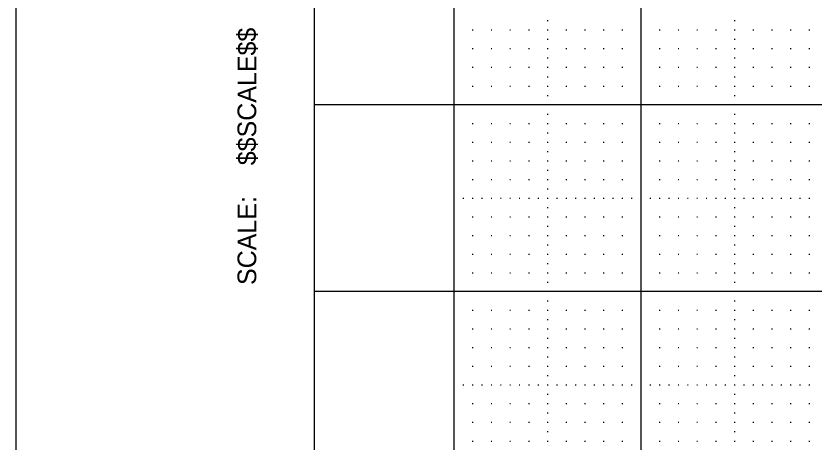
# Model space of a CAD drawing. Extents: x -1.6 to 32.4, y -0.7 to 21.3.
# Drawn here: x -1.598 to 2.67, y 2.487 to 4.768 of the extents above; entities that cross this region are included whole.
import ezdxf

# ---------------------------------------------------------------- set-up
doc = ezdxf.new("R2010")
doc.units = 0
for name, color, linetype in [('Level 1', 7, 'Continuous'), ('Level 5', 7, 'Continuous'), ('Level 63', 7, 'Continuous'), ('R_Border_Dark', 7, 'Continuous')]:
    doc.layers.add(name, color=color, linetype=linetype)

msp = doc.modelspace()

# ---------------------------------------------------------------- linework, layer by layer
at = {"layer": 'Level 1'}
msp.add_line((-0.001, -0.001), (-0.001, 20.545), dxfattribs=at)
at = {"layer": 'Level 5'}
for p, q in [((1.2425, 4.743), (1.2475, 4.743)), ((2.2425, 4.743), (2.2475, 4.743)), ((0.8425, 4.693), (0.8475, 4.693)), ((0.9425, 4.693), (0.9475, 4.693)), ((1.0425, 4.693), (1.0475, 4.693)), ((1.1425, 4.693), (1.1475, 4.693)), ((1.2425, 4.693), (1.2475, 4.693)), ((1.3425, 4.693), (1.3475, 4.693)), ((1.4425, 4.693), (1.4475, 4.693)), ((1.5425, 4.693), (1.5475, 4.693)), ((1.6425, 4.693), (1.6475, 4.693)), ((1.8425, 4.693), (1.8475, 4.693)), ((1.9425, 4.693), (1.9475, 4.693)), ((2.0425, 4.693), (2.0475, 4.693)), ((2.1425, 4.693), (2.1475, 4.693)), ((2.2425, 4.693), (2.2475, 4.693)), ((2.3425, 4.693), (2.3475, 4.693)), ((2.4425, 4.693), (2.4475, 4.693)), ((2.5425, 4.693), (2.5475, 4.693)), ((2.6425, 4.693), (2.6475, 4.693)), ((1.2425, 4.643), (1.2475, 4.643)), ((2.2425, 4.643), (2.2475, 4.643)), ((0.8425, 4.593), (0.8475, 4.593)), ((0.9425, 4.593), (0.9475, 4.593)), ((1.0425, 4.593), (1.0475, 4.593)), ((1.1425, 4.593), (1.1475, 4.593)), ((1.2425, 4.593), (1.2475, 4.593)), ((1.3425, 4.593), (1.3475, 4.593)), ((1.4425, 4.593), (1.4475, 4.593)), ((1.5425, 4.593), (1.5475, 4.593)), ((1.6425, 4.593), (1.6475, 4.593)), ((1.8425, 4.593), (1.8475, 4.593)), ((1.9425, 4.593), (1.9475, 4.593)), ((2.0425, 4.593), (2.0475, 4.593)), ((2.1425, 4.593), (2.1475, 4.593)), ((2.2425, 4.593), (2.2475, 4.593)), ((2.3425, 4.593), (2.3475, 4.593)), ((2.4425, 4.593), (2.4475, 4.593)), ((2.5425, 4.593), (2.5475, 4.593)), ((2.6425, 4.593), (2.6475, 4.593)), ((1.2425, 4.543), (1.2475, 4.543)), ((2.2425, 4.543), (2.2475, 4.543)), ((0.8425, 4.493), (0.8475, 4.493)), ((0.9425, 4.493), (0.9475, 4.493)), ((1.0425, 4.493), (1.0475, 4.493)), ((1.1425, 4.493), (1.1475, 4.493)), ((1.2425, 4.493), (1.2475, 4.493)), ((1.3425, 4.493), (1.3475, 4.493)), ((1.4425, 4.493), (1.4475, 4.493)), ((1.5425, 4.493), (1.5475, 4.493)), ((1.6425, 4.493), (1.6475, 4.493)), ((1.8425, 4.493), (1.8475, 4.493)), ((1.9425, 4.493), (1.9475, 4.493)), ((2.0425, 4.493), (2.0475, 4.493)), ((2.1425, 4.493), (2.1475, 4.493)), ((2.2425, 4.493), (2.2475, 4.493)), ((2.3425, 4.493), (2.3475, 4.493)), ((2.4425, 4.493), (2.4475, 4.493)), ((2.5425, 4.493), (2.5475, 4.493)), ((2.6425, 4.493), (2.6475, 4.493)), ((1.2425, 4.443), (1.2475, 4.443)), ((2.2425, 4.443), (2.2475, 4.443)), ((0.8425, 4.393), (0.8475, 4.393)), ((0.9425, 4.393), (0.9475, 4.393)), ((1.0425, 4.393), (1.0475, 4.393)), ((1.1425, 4.393), (1.1475, 4.393)), ((1.2425, 4.393), (1.2475, 4.393)), ((1.3425, 4.393), (1.3475, 4.393)), ((1.4425, 4.393), (1.4475, 4.393)), ((1.5425, 4.393), (1.5475, 4.393)), ((1.6425, 4.393), (1.6475, 4.393)), ((1.8425, 4.393), (1.8475, 4.393)), ((1.9425, 4.393), (1.9475, 4.393)), ((2.0425, 4.393), (2.0475, 4.393)), ((2.1425, 4.393), (2.1475, 4.393)), ((2.2425, 4.393), (2.2475, 4.393)), ((2.3425, 4.393), (2.3475, 4.393)), ((2.4425, 4.393), (2.4475, 4.393)), ((2.5425, 4.393), (2.5475, 4.393)), ((2.6425, 4.393), (2.6475, 4.393)), ((1.2425, 4.343), (1.2475, 4.343)), ((2.2425, 4.343), (2.2475, 4.343)), ((1.2425, 4.243), (1.2475, 4.243)), ((2.2425, 4.243), (2.2475, 4.243)), ((0.8425, 4.193), (0.8475, 4.193)), ((0.9425, 4.193), (0.9475, 4.193)), ((1.0425, 4.193), (1.0475, 4.193)), ((1.1425, 4.193), (1.1475, 4.193)), ((1.2425, 4.193), (1.2475, 4.193)), ((1.3425, 4.193), (1.3475, 4.193)), ((1.4425, 4.193), (1.4475, 4.193)), ((1.5425, 4.193), (1.5475, 4.193)), ((1.6425, 4.193), (1.6475, 4.193)), ((1.8425, 4.193), (1.8475, 4.193)), ((1.9425, 4.193), (1.9475, 4.193)), ((2.0425, 4.193), (2.0475, 4.193)), ((2.1425, 4.193), (2.1475, 4.193)), ((2.2425, 4.193), (2.2475, 4.193)), ((2.3425, 4.193), (2.3475, 4.193)), ((2.4425, 4.193), (2.4475, 4.193)), ((2.5425, 4.193), (2.5475, 4.193)), ((2.6425, 4.193), (2.6475, 4.193)), ((1.2425, 4.143), (1.2475, 4.143)), ((2.2425, 4.143), (2.2475, 4.143)), ((0.8425, 4.093), (0.8475, 4.093)), ((0.9425, 4.093), (0.9475, 4.093)), ((1.0425, 4.093), (1.0475, 4.093)), ((1.1425, 4.093), (1.1475, 4.093)), ((1.2425, 4.093), (1.2475, 4.093)), ((1.3425, 4.093), (1.3475, 4.093)), ((1.4425, 4.093), (1.4475, 4.093)), ((1.5425, 4.093), (1.5475, 4.093)), ((1.6425, 4.093), (1.6475, 4.093)), ((1.8425, 4.093), (1.8475, 4.093)), ((1.9425, 4.093), (1.9475, 4.093)), ((2.0425, 4.093), (2.0475, 4.093)), ((2.1425, 4.093), (2.1475, 4.093)), ((2.2425, 4.093), (2.2475, 4.093)), ((2.3425, 4.093), (2.3475, 4.093)), ((2.4425, 4.093), (2.4475, 4.093)), ((2.5425, 4.093), (2.5475, 4.093)), ((2.6425, 4.093), (2.6475, 4.093)), ((1.2425, 4.043), (1.2475, 4.043)), ((2.2425, 4.043), (2.2475, 4.043)), ((0.8425, 3.993), (0.8475, 3.993)), ((0.9425, 3.993), (0.9475, 3.993)), ((1.0425, 3.993), (1.0475, 3.993)), ((1.1425, 3.993), (1.1475, 3.993)), ((1.2425, 3.993), (1.2475, 3.993)), ((1.3425, 3.993), (1.3475, 3.993)), ((1.4425, 3.993), (1.4475, 3.993)), ((1.5425, 3.993), (1.5475, 3.993)), ((1.6425, 3.993), (1.6475, 3.993)), ((1.8425, 3.993), (1.8475, 3.993)), ((1.9425, 3.993), (1.9475, 3.993)), ((2.0425, 3.993), (2.0475, 3.993)), ((2.1425, 3.993), (2.1475, 3.993)), ((2.2425, 3.993), (2.2475, 3.993)), ((2.3425, 3.993), (2.3475, 3.993)), ((2.4425, 3.993), (2.4475, 3.993)), ((2.5425, 3.993), (2.5475, 3.993)), ((2.6425, 3.993), (2.6475, 3.993)), ((1.2425, 3.943), (1.2475, 3.943)), ((2.2425, 3.943), (2.2475, 3.943)), ((0.8425, 3.893), (0.8475, 3.893)), ((0.9425, 3.893), (0.9475, 3.893)), ((1.0425, 3.893), (1.0475, 3.893)), ((1.1425, 3.893), (1.1475, 3.893)), ((1.2425, 3.893), (1.2475, 3.893)), ((1.3425, 3.893), (1.3475, 3.893)), ((1.4425, 3.893), (1.4475, 3.893)), ((1.5425, 3.893), (1.5475, 3.893)), ((1.6425, 3.893), (1.6475, 3.893)), ((1.8425, 3.893), (1.8475, 3.893)), ((1.9425, 3.893), (1.9475, 3.893)), ((2.0425, 3.893), (2.0475, 3.893)), ((2.1425, 3.893), (2.1475, 3.893)), ((2.2425, 3.893), (2.2475, 3.893)), ((2.3425, 3.893), (2.3475, 3.893)), ((2.4425, 3.893), (2.4475, 3.893)), ((2.5425, 3.893), (2.5475, 3.893)), ((2.6425, 3.893), (2.6475, 3.893)), ((1.2425, 3.843), (1.2475, 3.843)), ((2.2425, 3.843), (2.2475, 3.843)), ((0.7925, 3.793), (0.7975, 3.793)), ((0.8425, 3.793), (0.8475, 3.793)), ((0.8925, 3.793), (0.8975, 3.793)), ((0.9425, 3.793), (0.9475, 3.793)), ((0.9925, 3.793), (0.9975, 3.793)), ((1.0425, 3.793), (1.0475, 3.793)), ((1.0925, 3.793), (1.0975, 3.793)), ((1.1425, 3.793), (1.1475, 3.793)), ((1.1925, 3.793), (1.1975, 3.793)), ((1.2425, 3.793), (1.2475, 3.793)), ((1.2925, 3.793), (1.2975, 3.793)), ((1.3425, 3.793), (1.3475, 3.793)), ((1.3925, 3.793), (1.3975, 3.793)), ((1.4425, 3.793), (1.4475, 3.793)), ((1.4925, 3.793), (1.4975, 3.793)), ((1.5425, 3.793), (1.5475, 3.793)), ((1.5925, 3.793), (1.5975, 3.793)), ((1.6425, 3.793), (1.6475, 3.793)), ((1.6925, 3.793), (1.6975, 3.793)), ((1.7925, 3.793), (1.7975, 3.793)), ((1.8425, 3.793), (1.8475, 3.793)), ((1.8925, 3.793), (1.8975, 3.793)), ((1.9425, 3.793), (1.9475, 3.793)), ((1.9925, 3.793), (1.9975, 3.793)), ((2.0425, 3.793), (2.0475, 3.793)), ((2.0925, 3.793), (2.0975, 3.793)), ((2.1425, 3.793), (2.1475, 3.793)), ((2.1925, 3.793), (2.1975, 3.793)), ((2.2425, 3.793), (2.2475, 3.793)), ((2.2925, 3.793), (2.2975, 3.793)), ((2.3425, 3.793), (2.3475, 3.793)), ((2.3925, 3.793), (2.3975, 3.793)), ((2.4425, 3.793), (2.4475, 3.793)), ((2.4925, 3.793), (2.4975, 3.793)), ((2.5425, 3.793), (2.5475, 3.793)), ((2.5925, 3.793), (2.5975, 3.793)), ((2.6425, 3.793), (2.6475, 3.793)), ((1.2425, 3.743), (1.2475, 3.743)), ((2.2425, 3.743), (2.2475, 3.743)), ((0.8425, 3.693), (0.8475, 3.693)), ((0.9425, 3.693), (0.9475, 3.693)), ((1.0425, 3.693), (1.0475, 3.693)), ((1.1425, 3.693), (1.1475, 3.693)), ((1.2425, 3.693), (1.2475, 3.693)), ((1.3425, 3.693), (1.3475, 3.693)), ((1.4425, 3.693), (1.4475, 3.693)), ((1.5425, 3.693), (1.5475, 3.693)), ((1.6425, 3.693), (1.6475, 3.693)), ((1.8425, 3.693), (1.8475, 3.693)), ((1.9425, 3.693), (1.9475, 3.693)), ((2.0425, 3.693), (2.0475, 3.693)), ((2.1425, 3.693), (2.1475, 3.693)), ((2.2425, 3.693), (2.2475, 3.693)), ((2.3425, 3.693), (2.3475, 3.693)), ((2.4425, 3.693), (2.4475, 3.693)), ((2.5425, 3.693), (2.5475, 3.693)), ((2.6425, 3.693), (2.6475, 3.693)), ((1.2425, 3.643), (1.2475, 3.643)), ((2.2425, 3.643), (2.2475, 3.643)), ((0.8425, 3.593), (0.8475, 3.593)), ((0.9425, 3.593), (0.9475, 3.593)), ((1.0425, 3.593), (1.0475, 3.593)), ((1.1425, 3.593), (1.1475, 3.593)), ((1.2425, 3.593), (1.2475, 3.593)), ((1.3425, 3.593), (1.3475, 3.593)), ((1.4425, 3.593), (1.4475, 3.593)), ((1.5425, 3.593), (1.5475, 3.593)), ((1.6425, 3.593), (1.6475, 3.593)), ((1.8425, 3.593), (1.8475, 3.593)), ((1.9425, 3.593), (1.9475, 3.593)), ((2.0425, 3.593), (2.0475, 3.593)), ((2.1425, 3.593), (2.1475, 3.593)), ((2.2425, 3.593), (2.2475, 3.593)), ((2.3425, 3.593), (2.3475, 3.593)), ((2.4425, 3.593), (2.4475, 3.593)), ((2.5425, 3.593), (2.5475, 3.593)), ((2.6425, 3.593), (2.6475, 3.593)), ((1.2425, 3.543), (1.2475, 3.543)), ((2.2425, 3.543), (2.2475, 3.543)), ((0.8425, 3.493), (0.8475, 3.493)), ((0.9425, 3.493), (0.9475, 3.493)), ((1.0425, 3.493), (1.0475, 3.493)), ((1.1425, 3.493), (1.1475, 3.493)), ((1.2425, 3.493), (1.2475, 3.493)), ((1.3425, 3.493), (1.3475, 3.493)), ((1.4425, 3.493), (1.4475, 3.493)), ((1.5425, 3.493), (1.5475, 3.493)), ((1.6425, 3.493), (1.6475, 3.493)), ((1.8425, 3.493), (1.8475, 3.493)), ((1.9425, 3.493), (1.9475, 3.493)), ((2.0425, 3.493), (2.0475, 3.493)), ((2.1425, 3.493), (2.1475, 3.493)), ((2.2425, 3.493), (2.2475, 3.493)), ((2.3425, 3.493), (2.3475, 3.493)), ((2.4425, 3.493), (2.4475, 3.493)), ((2.5425, 3.493), (2.5475, 3.493)), ((2.6425, 3.493), (2.6475, 3.493)), ((1.2425, 3.443), (1.2475, 3.443)), ((2.2425, 3.443), (2.2475, 3.443)), ((0.8425, 3.393), (0.8475, 3.393)), ((0.9425, 3.393), (0.9475, 3.393)), ((1.0425, 3.393), (1.0475, 3.393)), ((1.1425, 3.393), (1.1475, 3.393)), ((1.2425, 3.393), (1.2475, 3.393)), ((1.3425, 3.393), (1.3475, 3.393)), ((1.4425, 3.393), (1.4475, 3.393)), ((1.5425, 3.393), (1.5475, 3.393)), ((1.6425, 3.393), (1.6475, 3.393)), ((1.8425, 3.393), (1.8475, 3.393)), ((1.9425, 3.393), (1.9475, 3.393)), ((2.0425, 3.393), (2.0475, 3.393)), ((2.1425, 3.393), (2.1475, 3.393)), ((2.2425, 3.393), (2.2475, 3.393)), ((2.3425, 3.393), (2.3475, 3.393)), ((2.4425, 3.393), (2.4475, 3.393)), ((2.5425, 3.393), (2.5475, 3.393)), ((2.6425, 3.393), (2.6475, 3.393)), ((1.2425, 3.343), (1.2475, 3.343)), ((2.2425, 3.343), (2.2475, 3.343)), ((1.2425, 3.243), (1.2475, 3.243)), ((2.2425, 3.243), (2.2475, 3.243)), ((0.8425, 3.193), (0.8475, 3.193)), ((0.9425, 3.193), (0.9475, 3.193)), ((1.0425, 3.193), (1.0475, 3.193)), ((1.1425, 3.193), (1.1475, 3.193)), ((1.2425, 3.193), (1.2475, 3.193)), ((1.3425, 3.193), (1.3475, 3.193)), ((1.4425, 3.193), (1.4475, 3.193)), ((1.5425, 3.193), (1.5475, 3.193)), ((1.6425, 3.193), (1.6475, 3.193)), ((1.8425, 3.193), (1.8475, 3.193)), ((1.9425, 3.193), (1.9475, 3.193)), ((2.0425, 3.193), (2.0475, 3.193)), ((2.1425, 3.193), (2.1475, 3.193)), ((2.2425, 3.193), (2.2475, 3.193)), ((2.3425, 3.193), (2.3475, 3.193)), ((2.4425, 3.193), (2.4475, 3.193)), ((2.5425, 3.193), (2.5475, 3.193)), ((2.6425, 3.193), (2.6475, 3.193)), ((1.2425, 3.143), (1.2475, 3.143)), ((2.2425, 3.143), (2.2475, 3.143)), ((0.8425, 3.093), (0.8475, 3.093)), ((0.9425, 3.093), (0.9475, 3.093)), ((1.0425, 3.093), (1.0475, 3.093)), ((1.1425, 3.093), (1.1475, 3.093)), ((1.2425, 3.093), (1.2475, 3.093)), ((1.3425, 3.093), (1.3475, 3.093)), ((1.4425, 3.093), (1.4475, 3.093)), ((1.5425, 3.093), (1.5475, 3.093)), ((1.6425, 3.093), (1.6475, 3.093)), ((1.8425, 3.093), (1.8475, 3.093)), ((1.9425, 3.093), (1.9475, 3.093)), ((2.0425, 3.093), (2.0475, 3.093)), ((2.1425, 3.093), (2.1475, 3.093)), ((2.2425, 3.093), (2.2475, 3.093)), ((2.3425, 3.093), (2.3475, 3.093)), ((2.4425, 3.093), (2.4475, 3.093)), ((2.5425, 3.093), (2.5475, 3.093)), ((2.6425, 3.093), (2.6475, 3.093)), ((1.2425, 3.043), (1.2475, 3.043)), ((2.2425, 3.043), (2.2475, 3.043)), ((0.8425, 2.993), (0.8475, 2.993)), ((0.9425, 2.993), (0.9475, 2.993)), ((1.0425, 2.993), (1.0475, 2.993)), ((1.1425, 2.993), (1.1475, 2.993)), ((1.2425, 2.993), (1.2475, 2.993)), ((1.3425, 2.993), (1.3475, 2.993)), ((1.4425, 2.993), (1.4475, 2.993)), ((1.5425, 2.993), (1.5475, 2.993)), ((1.6425, 2.993), (1.6475, 2.993)), ((1.8425, 2.993), (1.8475, 2.993)), ((1.9425, 2.993), (1.9475, 2.993)), ((2.0425, 2.993), (2.0475, 2.993)), ((2.1425, 2.993), (2.1475, 2.993)), ((2.2425, 2.993), (2.2475, 2.993)), ((2.3425, 2.993), (2.3475, 2.993)), ((2.4425, 2.993), (2.4475, 2.993)), ((2.5425, 2.993), (2.5475, 2.993)), ((2.6425, 2.993), (2.6475, 2.993)), ((1.2425, 2.943), (1.2475, 2.943)), ((2.2425, 2.943), (2.2475, 2.943)), ((0.8425, 2.893), (0.8475, 2.893)), ((0.9425, 2.893), (0.9475, 2.893)), ((1.0425, 2.893), (1.0475, 2.893)), ((1.1425, 2.893), (1.1475, 2.893)), ((1.2425, 2.893), (1.2475, 2.893)), ((1.3425, 2.893), (1.3475, 2.893)), ((1.4425, 2.893), (1.4475, 2.893)), ((1.5425, 2.893), (1.5475, 2.893)), ((1.6425, 2.893), (1.6475, 2.893)), ((1.8425, 2.893), (1.8475, 2.893)), ((1.9425, 2.893), (1.9475, 2.893)), ((2.0425, 2.893), (2.0475, 2.893)), ((2.1425, 2.893), (2.1475, 2.893)), ((2.2425, 2.893), (2.2475, 2.893)), ((2.3425, 2.893), (2.3475, 2.893)), ((2.4425, 2.893), (2.4475, 2.893)), ((2.5425, 2.893), (2.5475, 2.893)), ((2.6425, 2.893), (2.6475, 2.893)), ((1.2425, 2.843), (1.2475, 2.843)), ((2.2425, 2.843), (2.2475, 2.843)), ((0.7925, 2.793), (0.7975, 2.793)), ((0.8425, 2.793), (0.8475, 2.793)), ((0.8925, 2.793), (0.8975, 2.793)), ((0.9425, 2.793), (0.9475, 2.793)), ((0.9925, 2.793), (0.9975, 2.793)), ((1.0425, 2.793), (1.0475, 2.793)), ((1.0925, 2.793), (1.0975, 2.793)), ((1.1425, 2.793), (1.1475, 2.793)), ((1.1925, 2.793), (1.1975, 2.793)), ((1.2425, 2.793), (1.2475, 2.793)), ((1.2925, 2.793), (1.2975, 2.793)), ((1.3425, 2.793), (1.3475, 2.793)), ((1.3925, 2.793), (1.3975, 2.793)), ((1.4425, 2.793), (1.4475, 2.793)), ((1.4925, 2.793), (1.4975, 2.793)), ((1.5425, 2.793), (1.5475, 2.793)), ((1.5925, 2.793), (1.5975, 2.793)), ((1.6425, 2.793), (1.6475, 2.793)), ((1.6925, 2.793), (1.6975, 2.793)), ((1.7925, 2.793), (1.7975, 2.793)), ((1.8425, 2.793), (1.8475, 2.793)), ((1.8925, 2.793), (1.8975, 2.793)), ((1.9425, 2.793), (1.9475, 2.793)), ((1.9925, 2.793), (1.9975, 2.793)), ((2.0425, 2.793), (2.0475, 2.793)), ((2.0925, 2.793), (2.0975, 2.793)), ((2.1425, 2.793), (2.1475, 2.793)), ((2.1925, 2.793), (2.1975, 2.793)), ((2.2425, 2.793), (2.2475, 2.793)), ((2.2925, 2.793), (2.2975, 2.793)), ((2.3425, 2.793), (2.3475, 2.793)), ((2.3925, 2.793), (2.3975, 2.793)), ((2.4425, 2.793), (2.4475, 2.793)), ((2.4925, 2.793), (2.4975, 2.793)), ((2.5425, 2.793), (2.5475, 2.793)), ((2.5925, 2.793), (2.5975, 2.793)), ((2.6425, 2.793), (2.6475, 2.793)), ((1.2425, 2.743), (1.2475, 2.743)), ((2.2425, 2.743), (2.2475, 2.743)), ((0.8425, 2.693), (0.8475, 2.693)), ((0.9425, 2.693), (0.9475, 2.693)), ((1.0425, 2.693), (1.0475, 2.693)), ((1.1425, 2.693), (1.1475, 2.693)), ((1.2425, 2.693), (1.2475, 2.693)), ((1.3425, 2.693), (1.3475, 2.693)), ((1.4425, 2.693), (1.4475, 2.693)), ((1.5425, 2.693), (1.5475, 2.693)), ((1.6425, 2.693), (1.6475, 2.693)), ((1.8425, 2.693), (1.8475, 2.693)), ((1.9425, 2.693), (1.9475, 2.693)), ((2.0425, 2.693), (2.0475, 2.693)), ((2.1425, 2.693), (2.1475, 2.693)), ((2.2425, 2.693), (2.2475, 2.693)), ((2.3425, 2.693), (2.3475, 2.693)), ((2.4425, 2.693), (2.4475, 2.693)), ((2.5425, 2.693), (2.5475, 2.693)), ((2.6425, 2.693), (2.6475, 2.693)), ((1.2425, 2.643), (1.2475, 2.643)), ((2.2425, 2.643), (2.2475, 2.643)), ((0.8425, 2.593), (0.8475, 2.593)), ((0.9425, 2.593), (0.9475, 2.593)), ((1.0425, 2.593), (1.0475, 2.593)), ((1.1425, 2.593), (1.1475, 2.593)), ((1.2425, 2.593), (1.2475, 2.593)), ((1.3425, 2.593), (1.3475, 2.593)), ((1.4425, 2.593), (1.4475, 2.593)), ((1.5425, 2.593), (1.5475, 2.593)), ((1.6425, 2.593), (1.6475, 2.593)), ((1.8425, 2.593), (1.8475, 2.593)), ((1.9425, 2.593), (1.9475, 2.593)), ((2.0425, 2.593), (2.0475, 2.593)), ((2.1425, 2.593), (2.1475, 2.593)), ((2.2425, 2.593), (2.2475, 2.593)), ((2.3425, 2.593), (2.3475, 2.593)), ((2.4425, 2.593), (2.4475, 2.593)), ((2.5425, 2.593), (2.5475, 2.593)), ((2.6425, 2.593), (2.6475, 2.593)), ((1.2425, 2.543), (1.2475, 2.543)), ((2.2425, 2.543), (2.2475, 2.543)), ((0.8425, 2.493), (0.8475, 2.493)), ((0.9425, 2.493), (0.9475, 2.493)), ((1.0425, 2.493), (1.0475, 2.493)), ((1.1425, 2.493), (1.1475, 2.493)), ((1.2425, 2.493), (1.2475, 2.493)), ((1.3425, 2.493), (1.3475, 2.493)), ((1.4425, 2.493), (1.4475, 2.493)), ((1.5425, 2.493), (1.5475, 2.493)), ((1.6425, 2.493), (1.6475, 2.493)), ((1.8425, 2.493), (1.8475, 2.493)), ((1.9425, 2.493), (1.9475, 2.493)), ((2.0425, 2.493), (2.0475, 2.493)), ((2.1425, 2.493), (2.1475, 2.493)), ((2.2425, 2.493), (2.2475, 2.493)), ((2.3425, 2.493), (2.3475, 2.493)), ((2.4425, 2.493), (2.4475, 2.493)), ((2.5425, 2.493), (2.5475, 2.493)), ((2.6425, 2.493), (2.6475, 2.493))]:
    msp.add_line(p, q, dxfattribs=at)
at = {"layer": 'Level 63'}
msp.add_lwpolyline([(-1.598, -0.727), (32.402, -0.727), (32.402, 21.273), (-1.598, 21.273)], close=True, dxfattribs=at)
msp.add_lwpolyline([(30.745, 8.293), (30.745, 0.293), (0.745, 0.293), (0.745, 8.293)], dxfattribs=at)
at = {"layer": 'R_Border_Dark'}
for p, q in [((0.745, 0.293), (0.745, 8.293)), ((1.745, 0.293), (1.745, 8.293)), ((31.617, 4.293), (-0.001, 4.293)), ((31.617, 3.293), (-0.001, 3.293))]:
    msp.add_line(p, q, dxfattribs=at)
msp.add_lwpolyline([(30.745, 8.293), (30.745, 0.293), (0.745, 0.293), (0.745, 8.293)], dxfattribs=at)

# ---------------------------------------------------------------- texts
at = {"layer": 'Level 1'}
for s, p in [('$$SCALE$$', (-0.313, 3.969)), ('SCALE:', (-0.313, 3.328))]:
    msp.add_text(s, height=0.1, rotation=90, dxfattribs=at).set_placement(p)

doc.saveas('drawing.dxf')
